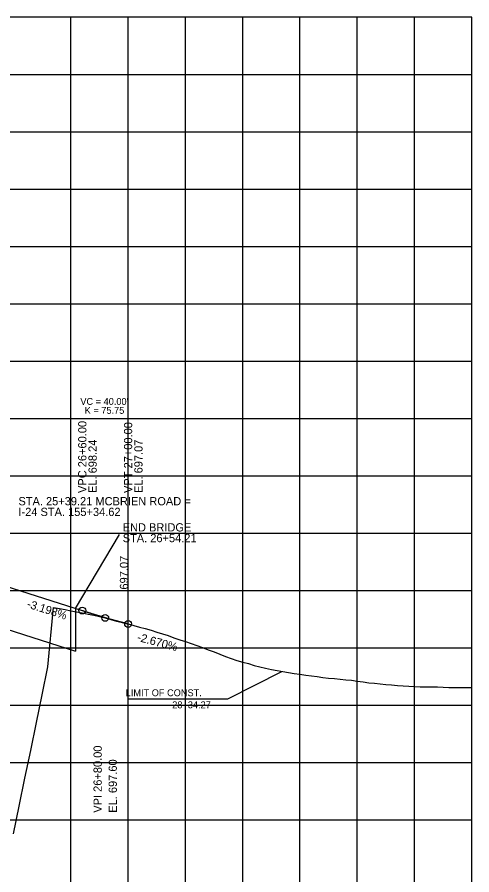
# Model space of a CAD drawing. Extents: x -7164 to 2214450, y -19642 to 253469.
# Drawn here: x 603 to 1000, y -8748 to -8000 of the extents above; entities that cross this region are included whole.
import ezdxf

# ---------------------------------------------------------------- set-up
doc = ezdxf.new("R2010")
doc.units = 0
for name, color, linetype in [('DESIGN - PROFILE - Proposed', 7, 'Continuous'), ('DESIGN - PROFILE - Proposed Curve Text', 7, 'Continuous'), ('DESIGN - PROFILE - Proposed Text', 7, 'Continuous'), ('DESIGN - SCRATCH - User 1', 7, 'Continuous'), ('DESIGN - SHEET - Light Grid', 7, 'Continuous'), ('SURVEY - PROFILE - Ground Line with Text', 7, 'Continuous')]:
    doc.layers.add(name, color=color, linetype=linetype)

msp = doc.modelspace()

# ---------------------------------------------------------------- linework, layer by layer
at = {"layer": 'DESIGN - PROFILE - Proposed'}
for p, q in [((580, -8491.98), (660, -8517.56)), ((580, -8491.98), (660, -8517.56)), ((654.21, -8515.71), (654.21, -8553.11)), ((654.21, -8515.71), (654.21, -8553.11)), ((569.15, -8525.91), (654.21, -8553.11)), ((569.15, -8525.91), (654.21, -8553.11)), ((699.99, -8594.56), (787, -8594.56)), ((699.99, -8594.56), (787, -8594.56))]:
    msp.add_line(p, q, dxfattribs=at)
msp.add_lwpolyline([(787, -8594.56), (834.27, -8570.64)], dxfattribs=at)
msp.add_lwpolyline([(787, -8594.56), (834.27, -8570.64)], dxfattribs=at)
msp.add_spline([(660, -8517.56), (660.8, -8517.81), (661.6, -8518.07), (662.4, -8518.32), (663.2, -8518.57), (664, -8518.83), (664.8, -8519.08), (665.6, -8519.33), (666.4, -8519.58), (667.2, -8519.83), (668, -8520.07), (668.8, -8520.32), (669.6, -8520.57), (670.4, -8520.81), (671.2, -8521.06), (672, -8521.3), (672.8, -8521.54), (673.6, -8521.78), (674.4, -8522.02), (675.2, -8522.26), (676, -8522.5), (676.8, -8522.74), (677.6, -8522.98), (678.4, -8523.22), (679.2, -8523.45), (680, -8523.69), (680.8, -8523.92), (681.6, -8524.16), (682.4, -8524.39), (683.2, -8524.62), (684, -8524.85), (684.8, -8525.08), (685.6, -8525.31), (686.4, -8525.54), (687.2, -8525.77), (688, -8525.99), (688.8, -8526.22), (689.6, -8526.44), (690.4, -8526.67), (691.2, -8526.89), (692, -8527.11), (692.8, -8527.34), (693.6, -8527.56), (694.4, -8527.78), (695.2, -8527.99), (696, -8528.21), (696.8, -8528.43), (697.6, -8528.65), (698.4, -8528.86), (699.2, -8529.08), (700, -8529.29)], degree=3, dxfattribs=at)
msp.add_spline([(660, -8517.56), (660.8, -8517.81), (661.6, -8518.07), (662.4, -8518.32), (663.2, -8518.57), (664, -8518.83), (664.8, -8519.08), (665.6, -8519.33), (666.4, -8519.58), (667.2, -8519.83), (668, -8520.07), (668.8, -8520.32), (669.6, -8520.57), (670.4, -8520.81), (671.2, -8521.06), (672, -8521.3), (672.8, -8521.54), (673.6, -8521.78), (674.4, -8522.02), (675.2, -8522.26), (676, -8522.5), (676.8, -8522.74), (677.6, -8522.98), (678.4, -8523.22), (679.2, -8523.45), (680, -8523.69), (680.8, -8523.92), (681.6, -8524.16), (682.4, -8524.39), (683.2, -8524.62), (684, -8524.85), (684.8, -8525.08), (685.6, -8525.31), (686.4, -8525.54), (687.2, -8525.77), (688, -8525.99), (688.8, -8526.22), (689.6, -8526.44), (690.4, -8526.67), (691.2, -8526.89), (692, -8527.11), (692.8, -8527.34), (693.6, -8527.56), (694.4, -8527.78), (695.2, -8527.99), (696, -8528.21), (696.8, -8528.43), (697.6, -8528.65), (698.4, -8528.86), (699.2, -8529.08), (700, -8529.29)], degree=3, dxfattribs=at)
at = {"layer": 'DESIGN - PROFILE - Proposed Text'}
for p, q in [((654.21, -8515.71), (692.59, -8451.17)), ((654.21, -8515.71), (692.59, -8451.17)), ((660, -8517.56), (677.14, -8523.04)), ((660, -8517.56), (677.14, -8523.04)), ((700, -8529.29), (682.9, -8524.73)), ((700, -8529.29), (682.9, -8524.73))]:
    msp.add_line(p, q, dxfattribs=at)
for centre in [(660, -8517.56), (660, -8517.56), (680, -8523.95), (680, -8523.95), (700, -8529.29), (700, -8529.29), (700, -8529.29), (700, -8529.29)]:
    msp.add_circle(centre, 3, dxfattribs=at)
at = {"layer": 'DESIGN - SCRATCH - User 1'}
for p, q in [((1000, -8000), (0, -8000)), ((1000, -8000), (0, -8000)), ((1000, -9000), (1000, -8000)), ((1000, -9000), (1000, -8000))]:
    msp.add_line(p, q, dxfattribs=at)
at = {"layer": 'DESIGN - SHEET - Light Grid'}
for p, q in [((650, -9000), (650, -8000)), ((650, -9000), (650, -8000)), ((700, -9000), (700, -8000)), ((700, -9000), (700, -8000)), ((750, -9000), (750, -8000)), ((750, -9000), (750, -8000)), ((800, -9000), (800, -8000)), ((800, -9000), (800, -8000)), ((850, -9000), (850, -8000)), ((850, -9000), (850, -8000)), ((900, -9000), (900, -8000)), ((900, -9000), (900, -8000)), ((950, -9000), (950, -8000)), ((950, -9000), (950, -8000)), ((0, -8050), (1000, -8050)), ((0, -8050), (1000, -8050)), ((0, -8100), (1000, -8100)), ((0, -8100), (1000, -8100)), ((0, -8150), (1000, -8150)), ((0, -8150), (1000, -8150)), ((0, -8200), (1000, -8200)), ((0, -8200), (1000, -8200)), ((0, -8250), (1000, -8250)), ((0, -8250), (1000, -8250)), ((0, -8300), (1000, -8300)), ((0, -8300), (1000, -8300)), ((0, -8350), (1000, -8350)), ((0, -8350), (1000, -8350)), ((0, -8400), (1000, -8400)), ((0, -8400), (1000, -8400)), ((0, -8450), (1000, -8450)), ((0, -8450), (1000, -8450)), ((0, -8500), (1000, -8500)), ((0, -8500), (1000, -8500)), ((0, -8550), (1000, -8550)), ((0, -8550), (1000, -8550)), ((0, -8600), (1000, -8600)), ((0, -8600), (1000, -8600)), ((0, -8650), (1000, -8650)), ((0, -8650), (1000, -8650)), ((0, -8700), (1000, -8700)), ((0, -8700), (1000, -8700))]:
    msp.add_line(p, q, dxfattribs=at)
at = {"layer": 'SURVEY - PROFILE - Ground Line with Text'}
msp.add_lwpolyline([(600, -8712.33), (605, -8688.1), (610, -8663.88), (615, -8639.63), (620, -8615.31), (625, -8591), (630, -8566.66), (635, -8514.79), (640, -8515.79), (645, -8516.75), (650, -8517.71), (655, -8518.66), (660, -8519.63), (665, -8520.61), (670, -8521.63), (675, -8522.74), (680, -8523.99), (685, -8525.34), (690, -8526.73), (695, -8528.03), (700, -8529.29), (705, -8530.63), (710, -8531.96), (715, -8533.33), (720, -8534.82), (725, -8536.34), (730, -8537.84), (735, -8539.46), (740, -8541.39), (745, -8543.09), (750, -8544.7), (755, -8546.41), (760, -8548.18), (765, -8549.85), (770, -8551.78), (775, -8553.74), (780, -8555.76), (785, -8557.67), (790, -8559.39), (795, -8561.04), (800, -8562.47), (805, -8563.92), (810, -8565.38), (815, -8566.7), (820, -8567.93), (825, -8568.99), (830, -8569.89), (835, -8570.77), (840, -8571.59), (845, -8572.44), (850, -8573.22), (855, -8573.93), (860, -8574.59), (865, -8575.22), (870, -8575.85), (875, -8576.46), (880, -8576.94), (885, -8577.39), (890, -8577.88), (895, -8578.36), (900, -8579.09), (905, -8579.89), (910, -8580.5), (915, -8581.02), (920, -8581.52), (925, -8581.96), (930, -8582.48), (935, -8582.96), (940, -8583.24), (945, -8583.52), (950, -8583.79), (955, -8584.04), (960, -8584.07), (965, -8584.12), (970, -8584.27), (975, -8584.42), (980, -8584.58), (985, -8584.71), (990, -8584.7), (995, -8584.67), (999, -8584.58)], dxfattribs=at)
msp.add_lwpolyline([(600, -8712.33), (605, -8688.1), (610, -8663.88), (615, -8639.63), (620, -8615.31), (625, -8591), (630, -8566.66), (635, -8514.79), (640, -8515.79), (645, -8516.75), (650, -8517.71), (655, -8518.66), (660, -8519.63), (665, -8520.61), (670, -8521.63), (675, -8522.74), (680, -8523.99), (685, -8525.34), (690, -8526.73), (695, -8528.03), (700, -8529.29), (705, -8530.63), (710, -8531.96), (715, -8533.33), (720, -8534.82), (725, -8536.34), (730, -8537.84), (735, -8539.46), (740, -8541.39), (745, -8543.09), (750, -8544.7), (755, -8546.41), (760, -8548.18), (765, -8549.85), (770, -8551.78), (775, -8553.74), (780, -8555.76), (785, -8557.67), (790, -8559.39), (795, -8561.04), (800, -8562.47), (805, -8563.92), (810, -8565.38), (815, -8566.7), (820, -8567.93), (825, -8568.99), (830, -8569.89), (835, -8570.77), (840, -8571.59), (845, -8572.44), (850, -8573.22), (855, -8573.93), (860, -8574.59), (865, -8575.22), (870, -8575.85), (875, -8576.46), (880, -8576.94), (885, -8577.39), (890, -8577.88), (895, -8578.36), (900, -8579.09), (905, -8579.89), (910, -8580.5), (915, -8581.02), (920, -8581.52), (925, -8581.96), (930, -8582.48), (935, -8582.96), (940, -8583.24), (945, -8583.52), (950, -8583.79), (955, -8584.04), (960, -8584.07), (965, -8584.12), (970, -8584.27), (975, -8584.42), (980, -8584.58), (985, -8584.71), (990, -8584.7), (995, -8584.67), (999, -8584.58)], dxfattribs=at)

# ---------------------------------------------------------------- texts
at = {"layer": 'DESIGN - PROFILE - Proposed'}
for s, p in [('LIMIT OF CONST.', (697.88, -8592.31)), ('LIMIT OF CONST.', (697.88, -8592.31)), ('28+34.27', (738.49, -8602.81)), ('28+34.27', (738.49, -8602.81))]:
    msp.add_text(s, height=6, dxfattribs=at).set_placement(p)
at = {"layer": 'DESIGN - PROFILE - Proposed Curve Text'}
for s, p in [("VC = 40.00'", (658.31, -8338.21)), ("VC = 40.00'", (658.31, -8338.21)), ('K = 75.75', (662.11, -8345.98)), ('K = 75.75', (662.11, -8345.98))]:
    msp.add_text(s, height=6, dxfattribs=at).set_placement(p)
for s, rotation, p in [('STA. 25+39.21 MCBRIEN ROAD =', 360, (604.27, -8425.81)), ('STA. 25+39.21 MCBRIEN ROAD =', 360, (604.27, -8425.81)), ('I-24 STA. 155+34.62', 360, (604.27, -8435.12)), ('I-24 STA. 155+34.62', 360, (604.27, -8435.12)), ('END BRIDGE', 360, (695.26, -8448.63)), ('END BRIDGE', 360, (695.26, -8448.63)), ('STA. 26+54.21', 360, (695.26, -8457.95)), ('STA. 26+54.21', 360, (695.26, -8457.95)), ('697.07', 90, (700, -8499.29)), ('697.07', 90, (700, -8499.29)), ('VPI 26+80.00', 90, (677, -8693.95)), ('VPI 26+80.00', 90, (677, -8693.95)), ('EL. 697.60', 90, (690.2, -8693.95)), ('EL. 697.60', 90, (690.2, -8693.95))]:
    msp.add_text(s, height=7.2, rotation=rotation, dxfattribs=at).set_placement(p)
at = {"layer": 'DESIGN - PROFILE - Proposed Text'}
for s, rotation, p in [('VPC 26+60.00 ', 90, (663.6, -8415.06)), ('VPC 26+60.00 ', 90, (663.6, -8415.06)), ('VPT 27+00.00 ', 90, (703.6, -8415.06)), ('VPT 27+00.00 ', 90, (703.6, -8415.06)), ('EL. 698.24', 90, (672.6, -8415.06)), ('EL. 698.24', 90, (672.6, -8415.06)), ('EL. 697.07', 90, (712.6, -8415.06)), ('EL. 697.07', 90, (712.6, -8415.06)), ('-3.198%', 342.26774, (611.12, -8514.74)), ('-3.198%', 342.26774, (611.12, -8514.74)), ('-2.670%', 345.05321, (707.37, -8543.89)), ('-2.670%', 345.05321, (707.37, -8543.89))]:
    msp.add_text(s, height=7.2, rotation=rotation, dxfattribs=at).set_placement(p)

doc.saveas('drawing.dxf')
